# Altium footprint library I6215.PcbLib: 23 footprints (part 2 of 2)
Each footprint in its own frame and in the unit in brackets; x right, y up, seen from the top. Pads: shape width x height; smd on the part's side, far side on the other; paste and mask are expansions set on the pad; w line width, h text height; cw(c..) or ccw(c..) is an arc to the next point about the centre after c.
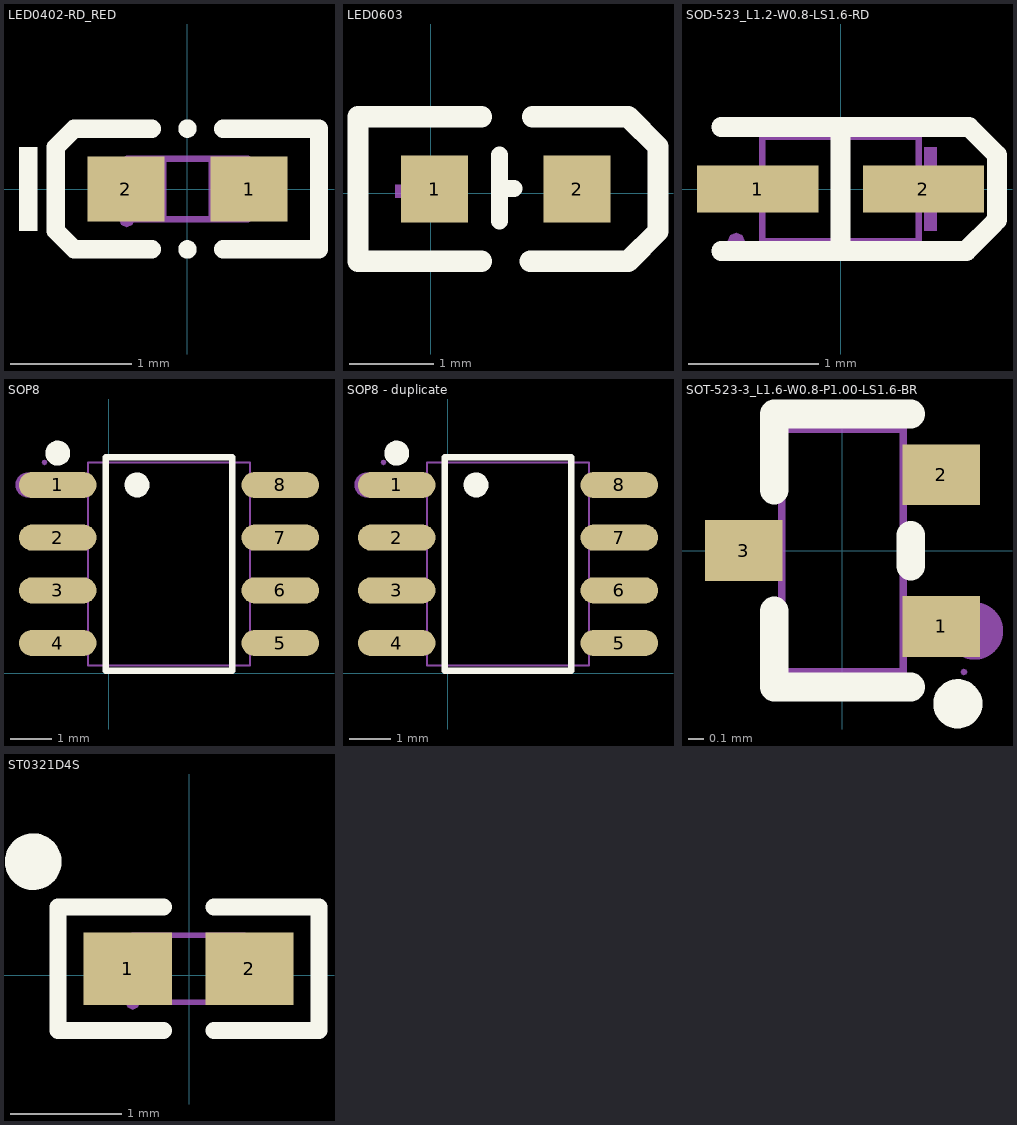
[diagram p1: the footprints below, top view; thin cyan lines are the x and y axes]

## LED0402-RD_RED [mm]
pads (2):
  rect 0.636x0.54 smd paste-100 mask+0.051: 1(0.508,0) 2(-0.508,0)
Top Overlay:
  circle w0.076: c0,0.499 r0.038
  circle w0.076: c0,-0.499 r0.038
  region: -1.237,-0.346 -1.237,0.346 -1.39,0.346 -1.39,-0.346
  lines w0.152: -0.296,-0.499 -0.933,-0.499 -1.085,-0.346 -1.085,0.346 -0.933,0.499 -0.296,0.499 ; 0.296,-0.499 1.085,-0.499 1.085,0.499 0.296,0.499
Top Paste:
  region: -0.168,-0.23 -0.168,0.23 -0.208,0.27 -0.786,0.27 -0.826,0.23 -0.826,-0.23 -0.786,-0.27 -0.208,-0.27
  region: 0.168,-0.23 0.168,0.23 0.208,0.27 0.786,0.27 0.826,0.23 0.826,-0.23 0.786,-0.27 0.208,-0.27
Mechanical 6:
  region: 0.35,-0.2 0.35,0.2 0.29,0.2 0.29,-0.2
  region: 0.44,-0.03 0.44,0.03 0.2,0.03 0.2,-0.03
  region: -0.44,-0.03 -0.44,0.03 -0.2,0.03 -0.2,-0.03
Mechanical 15:
  region: -0.435,-0.25 -0.454,-0.204 -0.5,-0.185 -0.546,-0.204 -0.565,-0.25 -0.546,-0.296 -0.5,-0.315 -0.454,-0.296
  region: -0.5,0.25 -0.5,-0.25 -0.175,-0.25 -0.175,0.25
  region: 0.175,-0.25 0.175,0.25 0.5,0.25 0.5,-0.25
  lines w0.051: -0.5,-0.25 -0.5,0.25 0.5,0.25 0.5,-0.25 -0.5,-0.25

## LED0603 [mm]
pads (2):
  rect 0.8x0.8 smd: 1(0.048,0.05) 2(1.75,0.05)
Top Overlay:
  lines w0.203: 0.823,-0.331 0.823,0.456 ; 0.823,0.058 0.998,0.058
  lines w0.254: 0.607,-0.814 -0.866,-0.814 -0.866,0.914 0.607,0.914 ; 1.191,-0.814 2.36,-0.814 2.715,-0.458 2.715,0.558 2.36,0.914 1.217,0.914
Mechanical 15:
  region: 0.239,-0.052 -0.422,-0.052 -0.422,0.101 0.239,0.101
  region: -0.036,0.325 -0.036,-0.335 -0.189,-0.335 -0.189,0.325
  region: 2.092,0 1.432,0 1.432,0.153 2.092,0.153

## SOD-523_L1.2-W0.8-LS1.6-RD [mm]
pads (2):
  rect 0.93x0.36 smd: 1(-0.635,0) 2(0.635,0)
Top Overlay:
  lines w0.152: -0.914,-0.476 -0.676,-0.476 0.963,-0.476 ; -0.914,0.476 -0.676,0.476 0.984,0.476 1.198,0.261 1.198,-0.238 ; 0.198,-0.476 0,-0.476 0,0.476 0.2,0.476 ; 0.963,-0.473 1.177,-0.259
Mechanical 6:
  region: -0.887,0.055 -0.887,-0.041 -0.503,-0.041 -0.503,0.055
  region: 0.88,0.048 0.88,-0.048 0.496,-0.048 0.496,0.048
  region: 0.736,0.32 0.736,-0.32 0.64,-0.32 0.64,0.32
Mechanical 15:
  region: -0.736,-0.4 -0.754,-0.355 -0.8,-0.336 -0.846,-0.355 -0.864,-0.4 -0.846,-0.445 -0.8,-0.464 -0.754,-0.445
  region: -0.8,-0.15 -0.8,0.15 -0.2,0.15 -0.2,-0.15
  region: 0.8,-0.15 0.8,0.15 0.2,0.15 0.2,-0.15
  lines w0.051: -0.6,-0.4 -0.6,0.4 0.6,0.4 0.6,-0.4 -0.6,-0.4

## SOP8 [mm]
height 6
pads (8):
  oval 1.865x0.63 smd: 1(-1.227,4.544) 2(-1.227,3.274) 3(-1.227,2.004) 4(-1.227,0.734) 5(4.138,0.734) 6(4.138,2.004) 7(4.138,3.274) 8(4.138,4.544)
Top Overlay:
  circle w0.3: c0.687,4.544 r0.15
  circle w0.3: c-1.227,5.311 r0.15
  lines w0.152: -0.065,0.062 2.977,0.062 2.977,5.215 -0.065,5.215 -0.065,0.062
Mechanical 6:
  circle w0.3: c-1.944,4.544 r0.15
Mechanical 15:
  region: -1.544,5.024 -1.498,5.043 -1.479,5.089 -1.498,5.135 -1.544,5.154 -1.59,5.135 -1.609,5.089 -1.59,5.043
  region: 3.396,0.944 3.631,0.944 3.631,0.524 3.396,0.524
  region: 3.621,0.944 4.456,0.944 4.456,0.524 3.621,0.524
  region: 3.396,2.214 3.631,2.214 3.631,1.794 3.396,1.794
  region: 3.621,2.214 4.456,2.214 4.456,1.794 3.621,1.794
  region: 3.396,3.484 3.631,3.484 3.631,3.064 3.396,3.064
  region: 3.621,3.484 4.456,3.484 4.456,3.064 3.621,3.064
  region: 3.396,4.754 3.631,4.754 3.631,4.334 3.396,4.334
  region: 3.621,4.754 4.456,4.754 4.456,4.334 3.621,4.334
  region: -0.719,0.944 -0.484,0.944 -0.484,0.524 -0.719,0.524
  region: -1.544,0.944 -0.709,0.944 -0.709,0.524 -1.544,0.524
  region: -0.719,2.214 -0.484,2.214 -0.484,1.794 -0.719,1.794
  region: -1.544,2.214 -0.709,2.214 -0.709,1.794 -1.544,1.794
  region: -0.719,3.484 -0.484,3.484 -0.484,3.064 -0.719,3.064
  region: -1.544,3.484 -0.709,3.484 -0.709,3.064 -1.544,3.064
  region: -0.719,4.754 -0.484,4.754 -0.484,4.334 -0.719,4.334
  region: -1.544,4.754 -0.709,4.754 -0.709,4.334 -1.544,4.334
  lines w0.051: -0.494,0.189 3.406,0.189 3.406,5.089 -0.494,5.089 -0.494,0.189

## SOP8 - duplicate [mm]
pads (8):
  oval 1.865x0.63 smd: 1(-1.227,4.544) 2(-1.227,3.274) 3(-1.227,2.004) 4(-1.227,0.734) 5(4.138,0.734) 6(4.138,2.004) 7(4.138,3.274) 8(4.138,4.544)
Top Overlay:
  circle w0.3: c0.687,4.544 r0.15
  circle w0.3: c-1.227,5.311 r0.15
  lines w0.152: -0.065,0.062 2.977,0.062 2.977,5.215 -0.065,5.215 -0.065,0.062
Mechanical 6:
  circle w0.3: c-1.944,4.544 r0.15
Mechanical 15:
  region: -1.544,5.024 -1.498,5.043 -1.479,5.089 -1.498,5.135 -1.544,5.154 -1.59,5.135 -1.609,5.089 -1.59,5.043
  region: 3.396,0.944 3.631,0.944 3.631,0.524 3.396,0.524
  region: 3.621,0.944 4.456,0.944 4.456,0.524 3.621,0.524
  region: 3.396,2.214 3.631,2.214 3.631,1.794 3.396,1.794
  region: 3.621,2.214 4.456,2.214 4.456,1.794 3.621,1.794
  region: 3.396,3.484 3.631,3.484 3.631,3.064 3.396,3.064
  region: 3.621,3.484 4.456,3.484 4.456,3.064 3.621,3.064
  region: 3.396,4.754 3.631,4.754 3.631,4.334 3.396,4.334
  region: 3.621,4.754 4.456,4.754 4.456,4.334 3.621,4.334
  region: -0.719,0.944 -0.484,0.944 -0.484,0.524 -0.719,0.524
  region: -1.544,0.944 -0.709,0.944 -0.709,0.524 -1.544,0.524
  region: -0.719,2.214 -0.484,2.214 -0.484,1.794 -0.719,1.794
  region: -1.544,2.214 -0.709,2.214 -0.709,1.794 -1.544,1.794
  region: -0.719,3.484 -0.484,3.484 -0.484,3.064 -0.719,3.064
  region: -1.544,3.484 -0.709,3.484 -0.709,3.064 -1.544,3.064
  region: -0.719,4.754 -0.484,4.754 -0.484,4.334 -0.719,4.334
  region: -1.544,4.754 -0.709,4.754 -0.709,4.334 -1.544,4.334
  lines w0.051: -0.494,0.189 3.406,0.189 3.406,5.089 -0.494,5.089 -0.494,0.189

## SOT-523-3_L1.6-W0.8-P1.00-LS1.6-BR [mm]
pads (3):
  rect 0.51x0.4 smd: 1(0.65,-0.5) 2(0.65,0.5) 3(-0.65,0)
Top Overlay:
  circle w0.19: c0.76,-1.01 r0.067
  lines w0.19: -0.45,-0.399 -0.45,-0.9 0.45,-0.9 0.45,-0.899 ; -0.45,0.399 -0.45,0.9 0.45,0.9 0.45,0.899 ; 0.45,-0.101 0.45,0.101
Mechanical 6:
  circle w0.19: c0.87,-0.53 r0.094
Mechanical 15:
  region: -0.8,-0.1 -0.8,0.1 -0.44,0.1 -0.44,-0.1
  region: -0.45,-0.1 -0.45,0.1 -0.39,0.1 -0.39,-0.1
  region: 0.44,-0.6 0.44,-0.4 0.8,-0.4 0.8,-0.6
  region: 0.39,-0.6 0.39,-0.4 0.45,-0.4 0.45,-0.6
  region: 0.44,0.4 0.44,0.6 0.8,0.6 0.8,0.4
  region: 0.39,0.4 0.39,0.6 0.45,0.6 0.45,0.4
  region: 0.821,-0.8 0.815,-0.786 0.8,-0.779 0.785,-0.786 0.779,-0.8 0.785,-0.814 0.8,-0.821 0.815,-0.814
  lines w0.051: -0.4,-0.8 -0.4,0.8 0.4,0.8 0.4,-0.8 -0.4,-0.8

## ST0321D4S [mm]
pads (2):
  rect 0.79x0.648 smd paste-100 mask+0.051: 1(-0.549,0.056) 2(0.541,0.056)
Top Overlay:
  circle w0.254: c-1.397,1.016 r0.127
  lines w0.152: -0.23,-0.497 -1.173,-0.497 -1.173,0.608 -0.23,0.608 ; 0.222,-0.497 1.165,-0.497 1.165,0.608 0.222,0.608
Top Paste:
  region: -0.139,-0.048 -0.139,0.159 -0.408,0.38 -0.896,0.38 -0.944,0.332 -0.944,-0.22 -0.896,-0.268 -0.408,-0.268
  region: 0.131,-0.048 0.131,0.159 0.399,0.38 0.888,0.38 0.936,0.332 0.936,-0.22 0.888,-0.268 0.399,-0.268
Mechanical 15:
  region: 0.496,-0.244 0.496,0.356 0.246,0.356 0.246,-0.244
  region: -0.504,-0.244 -0.504,0.356 -0.254,0.356 -0.254,-0.244
  region: -0.439,-0.244 -0.458,-0.198 -0.504,-0.179 -0.55,-0.198 -0.569,-0.244 -0.55,-0.29 -0.504,-0.309 -0.458,-0.29
  lines w0.051: -0.504,-0.244 0.496,-0.244 0.496,0.356 -0.504,0.356 -0.504,-0.244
